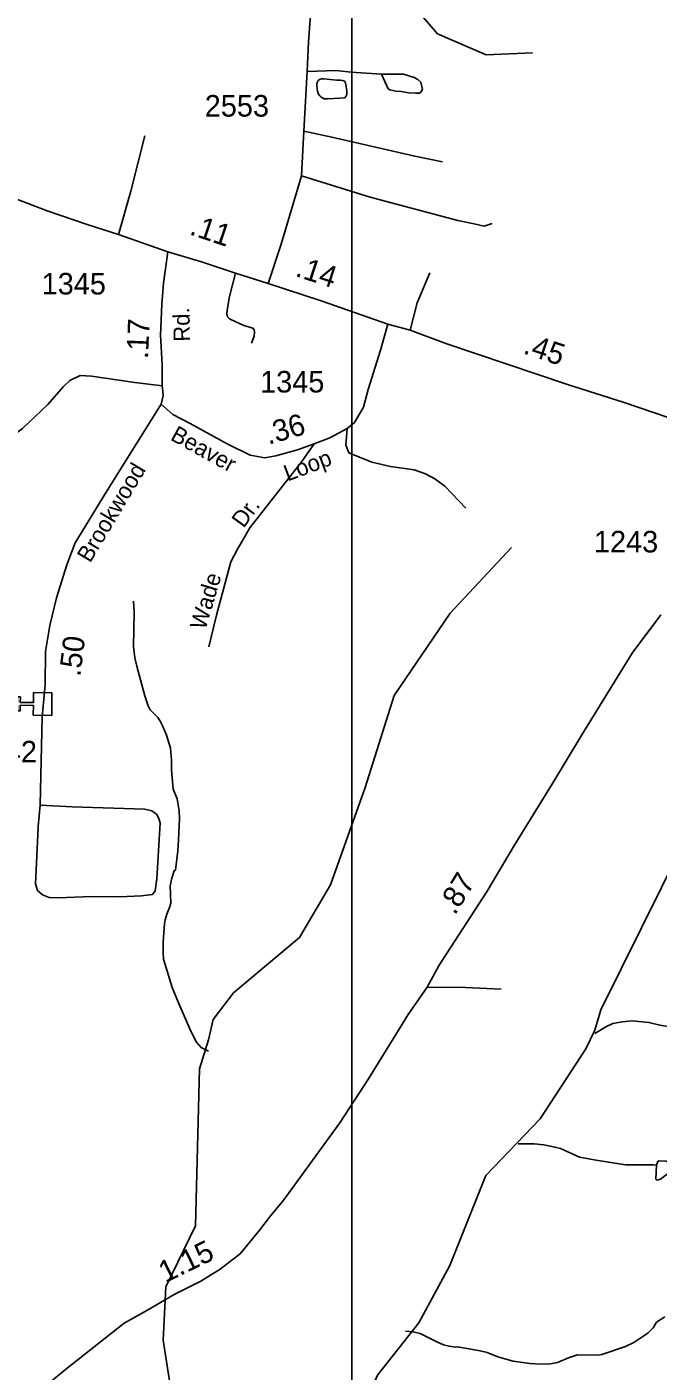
# Model space of a CAD drawing. Extents: x 1473865 to 1648260, y 639067 to 773536.
# Drawn here: x 1542250 to 1545902, y 657671 to 665451 of the extents above; entities that cross this region are included whole.
import ezdxf

# ---------------------------------------------------------------- set-up
doc = ezdxf.new("R2010")
doc.units = 0
for name, color, linetype in [('Exist Cultural Church CELL', 7, 'Continuous'), ('Exist Hydrographic Creek Single Shore', 7, 'Continuous'), ('Exist Hydrographic Misc Water Feature', 7, 'Continuous'), ('Exist Road Non-System Type 51', 7, 'Continuous'), ('Exist Road Non-System Type 51 Label', 7, 'Continuous'), ('Exist Road Primary NC Attributed', 7, 'Continuous'), ('Exist Road Primary NC Service Mileage Hundredths English Label', 7, 'Continuous'), ('Exist Road Secondary Mileage Hundredths English Label', 7, 'Continuous'), ('Exist Road Secondary Type 51 Attributed', 7, 'Continuous'), ('Exist Road Secondary Type 51 Label', 7, 'Continuous'), ('Exist Road Secondary Type 51 Number Label', 7, 'Continuous'), ('Map Preparation Inset Cut Line', 7, 'Continuous')]:
    doc.layers.add(name, color=color, linetype=linetype)

msp = doc.modelspace()

# ---------------------------------------------------------------- linework, layer by layer
at = {"layer": 'Exist Cultural Church CELL'}
msp.add_lwpolyline([(1542287.3, 661467.2), (1542288, 661524.1), (1542211.8, 661525), (1542211.4, 661493), (1542195.4, 661493.3), (1542195.8, 661525.2), (1542135.7, 661526), (1542135.9, 661542), (1542196, 661541.3), (1542196.5, 661573.3), (1542212.4, 661573.1), (1542212, 661541.1), (1542288.2, 661540.1), (1542289, 661597.8), (1542395.4, 661596.4), (1542393.8, 661465.8)], close=True, dxfattribs=at)
at = {"layer": 'Exist Hydrographic Creek Single Shore'}
for points in [[(1545174.3, 665300.6), (1544907.2, 665289.5), (1544626.3, 665410.1), (1544479.3, 665580.5)], [(1543432.1, 655767.4), (1543399.1, 655810.7), (1543410.1, 655984.4), (1543471.1, 656157.2), (1543420.2, 656584.9), (1543241.2, 656870.8), (1543204.1, 657186.7), (1543108.1, 657405.3), (1543039.1, 657849.8), (1543053.1, 658158), (1543225.2, 658512.4), (1543248.1, 659421.2), (1543300.1, 659587.5), (1543327.2, 659705.1), (1543446.1, 659860.3), (1543827.2, 660180.9), (1544006.2, 660485.8), (1544207.2, 661049.6), (1544374.2, 661581.3), (1544698.1, 662057.2), (1545054.2, 662437.4)]]:
    msp.add_lwpolyline(points, dxfattribs=at)
at = {"layer": 'Exist Hydrographic Misc Water Feature'}
for points in [[(1544041.6, 665142.1), (1544063.7, 665141.6), (1544075.6, 665141.3), (1544083.5, 665139.5), (1544091.4, 665133.6), (1544095.2, 665115.5), (1544098.9, 665094.9), (1544100.6, 665079.3), (1544100.4, 665058.8), (1544096.2, 665047.4), (1544090.2, 665040.9), (1544059.9, 665037.4), (1543989.9, 665034.8), (1543969.8, 665035.2), (1543960.1, 665039.5), (1543952, 665043.7), (1543944.1, 665051.3), (1543936.3, 665061.3), (1543930.5, 665079.5), (1543927.1, 665109.9), (1543927.3, 665119.7), (1543929.5, 665129.5), (1543935.7, 665140.1), (1543943.8, 665145.6), (1543955.8, 665149.5), (1543967.9, 665149.3), (1544041.6, 665142.1)], [(1543300.9, 659523.5), (1543259.1, 659544), (1543231.6, 659574.1), (1543223.8, 659589), (1543192.8, 659652.9), (1543127, 659801.9), (1543090.4, 659891.2), (1543041, 660055.5), (1543037.7, 660093.4), (1543038.8, 660155.7), (1543046.2, 660259.8), (1543050.6, 660283.5), (1543059.3, 660315.3), (1543075.9, 660355.2), (1543082.2, 660378.8), (1543079.8, 660479), (1543088.5, 660523.2), (1543103, 660567.2), (1543109.3, 660571.1), (1543123, 660682.5), (1543128.1, 660746.4), (1543134, 660866.9), (1543130.6, 660914.5), (1543119.7, 660982.9), (1543096.6, 661039.2), (1543086.4, 661151.8), (1543087.4, 661207.6), (1543080.3, 661275.8), (1543057.6, 661351.8), (1543038.3, 661398.1), (1543018.9, 661436.2), (1543007.1, 661452.9), (1542963.7, 661497.3), (1542952.1, 661521.3), (1542933.2, 661579.9), (1542906.5, 661672.4), (1542885.8, 661750.8), (1542874.4, 661799.4), (1542867.5, 661865.2), (1542870.7, 662062.9), (1542867.8, 662127)], [(1543432.1, 655767.4), (1543516.1, 655798.5), (1543602.1, 656006.8), (1543648.1, 656255.4), (1543871.1, 656651.3), (1543874.1, 656851.4), (1544114.2, 657283.2), (1544279.1, 657647.6), (1544517.1, 657951.2), (1544697.1, 658282.4), (1544905.1, 658803.4), (1545219.2, 659131.9), (1545484.2, 659536.9), (1545535.2, 659644.1), (1545571.2, 659761.6), (1546156.2, 660944.6), (1546335.2, 661180.7), (1546530.2, 661386.8), (1546559.2, 661635.7), (1546602.2, 661726.7), (1546837.3, 661856.5)], [(1545535.2, 659624.5), (1545600, 659663.4), (1545640.2, 659682.2), (1545694.4, 659693.5), (1545752.5, 659698.8), (1545848.5, 659689.5), (1545912.2, 659672.6), (1546016, 659655), (1546069.9, 659653.9)], [(1545093.2, 658986.7), (1545185, 658985.7), (1545241.1, 658980.4), (1545304.9, 658967.7), (1545336.7, 658958.9), (1545447.9, 658909), (1545543.8, 658891.5), (1545651.5, 658874.5), (1545715.3, 658865), (1545763.4, 658864.1), (1545875.4, 658864.3), (1545893.4, 658862.3)], [(1545893.4, 658862.3), (1545888.3, 658782.8), (1545894.1, 658776.1), (1545916.2, 658782.2), (1545972.9, 658825.4), (1545987.1, 658839.1), (1545989.4, 658850.5), (1545989.4, 658858.7), (1545977.7, 658872.9), (1545973.7, 658877), (1545945.8, 658885.8), (1545907.9, 658888.2), (1545899.8, 658884.3), (1545895.7, 658874.5), (1545893.4, 658862.3)], [(1544439.8, 657902.7), (1544485.6, 657897.7), (1544525.5, 657889.5), (1544620.9, 657840), (1544660.6, 657823.6), (1544692.4, 657814.8), (1544732.3, 657809.9), (1544740.4, 657812.2), (1544872.2, 657788.2), (1544912, 657779.1), (1544975.5, 657754.1), (1545015.5, 657741.8), (1545063.2, 657728.5), (1545159.1, 657715.1), (1545223.1, 657712.1), (1545279.2, 657713.5), (1545319.3, 657720.9), (1545383.6, 657747.5), (1545435.9, 657765.3), (1545552, 657762.9), (1545576.1, 657766.6), (1545712.7, 657813.1), (1545761.2, 657835.9), (1545842.1, 657890.8), (1545872.6, 657922.3), (1545893.1, 657953.8), (1545941.7, 657984.9)]]:
    msp.add_lwpolyline(points, dxfattribs=at)
at = {"layer": 'Exist Road Non-System Type 51'}
for points in [[(1543872.2, 665193.2), (1544039.7, 665198.1), (1544125.6, 665188.7), (1544302.1, 665176.2)], [(1544302.1, 665176.2), (1544428.6, 665176.2), (1544491.1, 665157.4), (1544511.4, 665146.5), (1544530.1, 665130.8), (1544537.9, 665088.6), (1544527, 665070.2), (1544522.3, 665066.7), (1544498.9, 665066.7), (1544459.9, 665069.9), (1544414.6, 665077.7), (1544384.9, 665079.3), (1544350.5, 665085.5), (1544340.2, 665092.3), (1544302.1, 665176.2)], [(1542933.2, 664819.4), (1542851.3, 664500.9), (1542780, 664249.8)], [(1544653.7, 664670.7), (1544493.6, 664702), (1544015, 664812.6), (1543851.6, 664847.7)], [(1544941.5, 664313), (1544895.2, 664298), (1544837.2, 664310.8), (1544743.7, 664330.4), (1544236.5, 664464.5), (1543838.8, 664588)], [(1543550.3, 663620.5), (1543565.1, 663660.3), (1543567.6, 663686.2), (1543564.5, 663697.9), (1543558, 663706.2), (1543504.4, 663723.3), (1543431, 663756.6), (1543419.7, 663763.9), (1543411.3, 663773), (1543407, 663789.9), (1543407.9, 663811.1), (1543421.5, 663890.9), (1543457.6, 664025)], [(1544582.2, 664027.9), (1544508.9, 663853.5), (1544467.3, 663695.9)], [(1541315.2, 662371), (1541555.9, 662669.9), (1541648.5, 662762.7), (1541824.3, 662857.4), (1542050.8, 662998.9), (1542225.3, 663125.6), (1542371.7, 663264.7), (1542461.7, 663369.2), (1542498.4, 663404.5), (1542558.8, 663433.2), (1542624.8, 663429.9), (1542874.2, 663393.3), (1543033.7, 663374.2)], [(1544790.4, 662665.5), (1544668.7, 662793.6), (1544609.5, 662834.8), (1544556.1, 662863.7), (1544490.5, 662887), (1544352.9, 662905.6), (1544245.3, 662931.6), (1544112.4, 662986.1), (1544095.2, 663030.5), (1544103, 663126.2)], [(1543911.3, 663037.8), (1543841.7, 662935.9), (1543539.2, 662552), (1543467.9, 662427.6), (1543430.6, 662354.4), (1543347.4, 662046.4), (1543303.5, 661863.7)], [(1542313.7, 660775.7), (1542299.7, 660491), (1542311.2, 660452.8), (1542340.7, 660428.4), (1542378.4, 660411.6), (1542430.4, 660410.5), (1542626.4, 660417), (1542786.4, 660416), (1542912.4, 660421.4), (1542976.6, 660430.3), (1542993, 660450), (1543002.2, 660519.9), (1543020.4, 660843.3), (1543013.7, 660868.4), (1542999.2, 660893.7), (1542973.6, 660914.2), (1542931.7, 660922.9), (1542512.2, 660937), (1542326.3, 660946.3)], [(1544994.1, 659882.4), (1544788.4, 659890.3), (1544565.7, 659893)]]:
    msp.add_lwpolyline(points, dxfattribs=at)
at = {"layer": 'Exist Road Primary NC Attributed'}
for points in [[(1540390.7, 665571.2), (1540857.6, 665266.1), (1541140.1, 665072.1), (1541355.2, 664928.7), (1541576.4, 664782.5), (1541710.8, 664700), (1541873, 664606.9), (1542011.5, 664530.2), (1542186.1, 664455.1), (1542366.8, 664385.6), (1542599.1, 664307.3), (1542780, 664249.8), (1543066.1, 664148.4)], [(1543066.1, 664148.4), (1543261.1, 664090.8), (1543457.6, 664025), (1543646.5, 663965.4)], [(1543646.5, 663965.4), (1543952.6, 663865.8), (1544337.9, 663730.3)], [(1544337.9, 663730.3), (1544467.3, 663695.9), (1544673.8, 663618.1), (1545377.1, 663380.8), (1545699, 663278.7), (1546577.2, 662980.2)]]:
    msp.add_lwpolyline(points, dxfattribs=at)
at = {"layer": 'Exist Road Secondary Type 51 Attributed'}
for points in [[(1543646.5, 663965.4), (1543721.3, 664192.4), (1543838.8, 664588), (1543851.6, 664847.7), (1543872.2, 665193.2), (1543879.5, 665365.2), (1543903.7, 665704.7), (1543916.9, 665972.3), (1543938.3, 666257.8), (1543950, 666567.5), (1543967.6, 666865.1), (1543990.6, 667338.5), (1544001.8, 667510.4), (1544012.9, 667782.1), (1544029.2, 667890.4), (1544043.2, 667949.7)], [(1543066.1, 664148.4), (1543040.9, 663968), (1543030.6, 663846.1), (1543023.2, 663666.4), (1543032.1, 663496.3), (1543033.7, 663374.2), (1543035.1, 663359), (1543038.8, 663318.3), (1543027.7, 663266.5)], [(1543027.7, 663266.5), (1543094.7, 663207.1), (1543195.7, 663155.3), (1543409.5, 663037.3), (1543542.2, 662972.8), (1543625.9, 662957.3), (1543690.2, 662968), (1543814.8, 663003.7), (1543911.3, 663037.8), (1544002, 663072.2), (1544103, 663126.2), (1544145.7, 663161.3), (1544197.3, 663250.3), (1544225.2, 663351.8), (1544295.4, 663580.5), (1544337.9, 663730.3)], [(1543027.7, 663266.5), (1542707.9, 662757.7), (1542529.6, 662465.7), (1542481.1, 662336.5), (1542421.7, 662147.2), (1542382.5, 661986.3), (1542358.1, 661836.2), (1542356.1, 661643.3), (1542338.6, 661457.8), (1542326.3, 660946.3), (1542316, 660822.7), (1542313.7, 660775.7)], [(1545917.9, 662048.8), (1545751.7, 661826.1), (1545461.1, 661353.7), (1545291.7, 661071), (1545067.1, 660709.3), (1544912.1, 660448.3), (1544636.1, 660019.7), (1544565.7, 659893), (1544456.9, 659735.2), (1544225.9, 659363.6), (1544061.1, 659108.8), (1543736.9, 658662.9), (1543654.1, 658561.7), (1543596.9, 658488.4), (1543483.1, 658349.9), (1543436.2, 658313.5), (1543367.4, 658260.2), (1543256.2, 658192.2), (1543102.7, 658115.1), (1542945, 658022.2), (1542813.6, 657948.6), (1542472.7, 657681.1), (1542277.7, 657519)]]:
    msp.add_lwpolyline(points, dxfattribs=at)
at = {"layer": 'Map Preparation Inset Cut Line'}
for points in [[(1481537.9, 640573), (1544130.8, 640573), (1544130.8, 678673.7), (1481537.9, 678673.7), (1481537.9, 640573)], [(1544130.8, 639067.3), (1606587.1, 639067.3), (1606587.1, 678673.7), (1544130.8, 678673.7), (1544130.8, 639067.3)]]:
    msp.add_lwpolyline(points, dxfattribs=at)

# ---------------------------------------------------------------- texts
at = {"layer": 'Exist Road Non-System Type 51 Label'}
for s, rotation, p in [('Dr.', 53.92494, (1543504.2, 662545.5)), ('Wade', 73.51982, (1543282.8, 661956.4))]:
    msp.add_text(s, height=95, rotation=rotation, dxfattribs=at).set_placement(p)
at = {"layer": 'Exist Road Primary NC Service Mileage Hundredths English Label'}
for s, rotation, p in [('.11', 341.49393, (1543185.4, 664251.2)), ('.14', 341.97404, (1543797.1, 664009.7)), ('.45', 341.35636, (1545115.7, 663562.9))]:
    msp.add_text(s, height=125, rotation=rotation, dxfattribs=at).set_placement(p)
at = {"layer": 'Exist Road Secondary Mileage Hundredths English Label'}
for s, rotation, p in [('.17', 87.63254, (1542950.9, 663527.4)), ('.36', 15.99267, (1543647.5, 663032.3)), ('.50', 82.95062, (1542559.1, 661687.3)), ('.87', 58.15689, (1544726.1, 660306)), ('1.15', 26.00899, (1543051.4, 658179.6))]:
    msp.add_text(s, height=125, rotation=rotation, dxfattribs=at).set_placement(p)
at = {"layer": 'Exist Road Secondary Type 51 Label'}
for s, rotation, p in [('Rd.', 91.20935, (1543194.4, 663629.9)), ('Beaver', 331.10224, (1543074.6, 663063.7)), ('Brookwood', 59.13083, (1542615.9, 662344.1)), ('Loop', 20.75489, (1543758.3, 662819.2))]:
    msp.add_text(s, height=95, rotation=rotation, dxfattribs=at).set_placement(p)
at = {"layer": 'Exist Road Secondary Type 51 Number Label'}
for s, p in [('2553', (1543279, 664931.5)), ('1345', (1542335.5, 663902)), ('1345', (1543599.4, 663334.7)), ('1243', (1545530.6, 662409.1)), ('1442', (1541936.6, 661193.7))]:
    msp.add_text(s, height=125, dxfattribs=at).set_placement(p)

doc.saveas('drawing.dxf')
